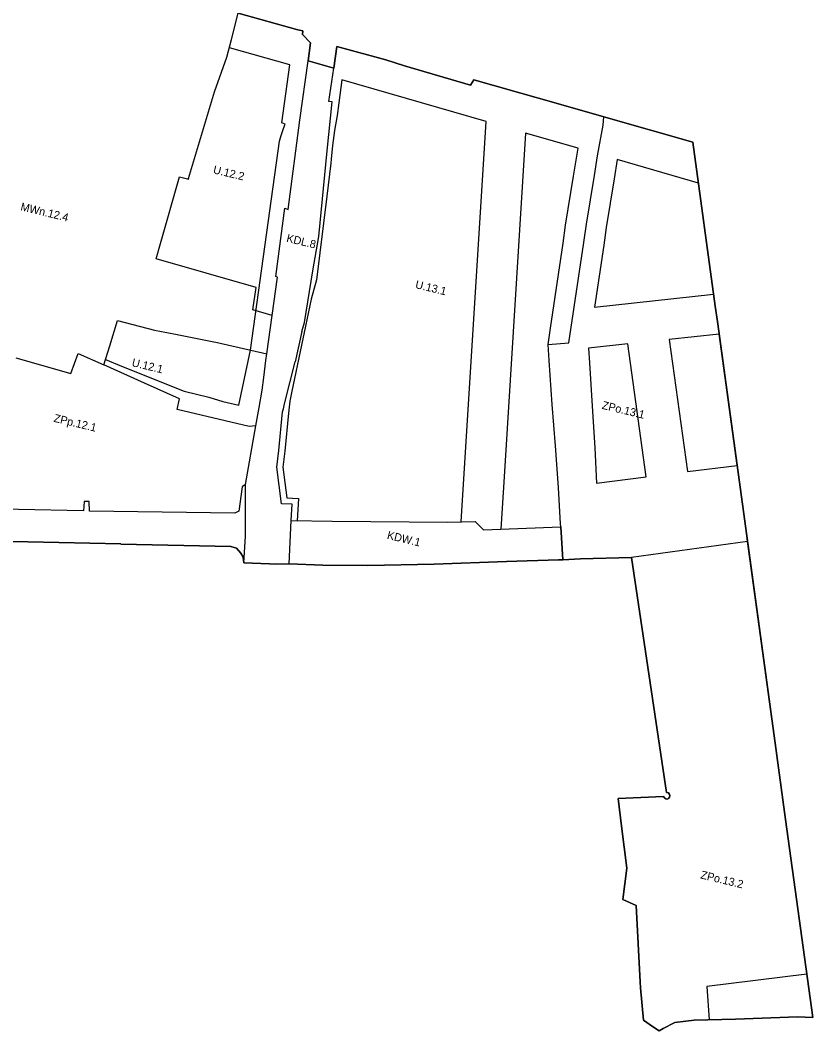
# Model space of a CAD drawing. Extents: x 7429686 to 7432896, y 5547954 to 5550600.
# Drawn here: x 7432024 to 7432420, y 5547954 to 5548459 of the extents above; entities that cross this region are included whole.
import ezdxf

# ---------------------------------------------------------------- set-up
doc = ezdxf.new("R2010")
doc.units = 0
for name, color, linetype in [('granica planu', 7, 'Continuous'), ('linie rozgraniczające', 7, 'Continuous'), ('nieprzekraczalna linia zabudowy', 7, 'Continuous'), ('obowiązująca linia zabudowy', 7, 'Continuous'), ('oznaczenia przeznaczeń', 7, 'Continuous')]:
    doc.layers.add(name, color=color, linetype=linetype)

msp = doc.modelspace()

# ---------------------------------------------------------------- linework, layer by layer
at = {"layer": 'granica planu'}
for p, q in [((7432315.39, 5548410.83), (7432359.79, 5548398.14)), ((7432359.79, 5548398.14), (7432371.02, 5548316.2)), ((7432347.59, 5548073.07), (7432346.66, 5548073.23)), ((7432346.27, 5548070.07), (7432346.93, 5548069.95)), ((7432412.06, 5547961.21), (7432381.17, 5547959.91)), ((7432419.73, 5547960.86), (7432412.06, 5547961.21))]:
    msp.add_line(p, q, dxfattribs=at)
for points in [[(7432200, 5548492.94), (7432194.33, 5548494.21), (7432194.14, 5548494.25), (7432168.86, 5548499.89), (7432167.55, 5548495.53), (7432161.04, 5548497.78), (7432158.03, 5548498.87), (7432144.51, 5548502.39), (7432143.43, 5548498.33), (7432132.81, 5548462.54), (7432162.54, 5548454.18), (7432165.08, 5548453.77), (7432164.94, 5548451.89), (7432168.88, 5548447.76), (7432167.65, 5548438.77), (7432180.47, 5548435.15), (7432182.05, 5548445.83)], [(7432182.05, 5548445.83), (7432206.42, 5548439.24), (7432215.81, 5548436.28), (7432248.72, 5548426.59), (7432250.42, 5548429.24), (7432260.46, 5548426.4), (7432273.9, 5548422.59), (7432290.34, 5548417.93), (7432315.39, 5548410.83)], [(7432371.02, 5548316.2), (7432372.06, 5548308.58), (7432386.76, 5548201.48)], [(7432303.72, 5548189.91), (7432294.92, 5548189.52), (7432292.68, 5548189.45), (7432266.77, 5548188.67), (7432230.6, 5548187.3), (7432197.45, 5548186.59), (7432175.07, 5548186.85), (7432158.14, 5548187.52), (7432151.44, 5548187.26), (7432148.44, 5548187.52), (7432135.5, 5548187.9), (7432135.19, 5548190.78), (7432134, 5548192.82), (7432131.92, 5548195.24), (7432128.99, 5548196.14), (7432074.08, 5548197.22), (7432074.05, 5548197.49), (7431996.63, 5548199.16)], [(7432386.76, 5548201.48), (7432400.46, 5548101.47), (7432406.18, 5548059.78), (7432419.73, 5547960.86)], [(7432346.66, 5548073.23), (7432329.11, 5548190.62), (7432303.72, 5548189.91)], [(7432348.09, 5548070.8), (7432348.27, 5548071.63), (7432348.19, 5548072.26), (7432347.59, 5548073.07)], [(7432326.78, 5548035.46), (7432324.19, 5548056.45), (7432322.49, 5548070.25), (7432345.23, 5548071.22)], [(7432345.23, 5548071.22), (7432345.66, 5548070.55), (7432346.27, 5548070.07)], [(7432346.93, 5548069.95), (7432347.66, 5548070.18), (7432348.09, 5548070.8)], [(7432333.76, 5547975.57), (7432333.51, 5547978.59), (7432331.44, 5548016.74), (7432324.8, 5548019.76), (7432326.78, 5548035.46)], [(7432339.64, 5547956.29), (7432335.23, 5547959.54), (7432333.76, 5547975.57)], [(7432356.29, 5547959), (7432350.86, 5547958.24), (7432344.94, 5547955.25)], [(7432381.17, 5547959.91), (7432360.54, 5547959.47), (7432356.29, 5547959)], [(7432344.94, 5547955.25), (7432342.97, 5547954.16), (7432339.64, 5547956.29)]]:
    msp.add_lwpolyline(points, dxfattribs=at)
at = {"layer": 'linie rozgraniczające'}
for p, q in [((7432164.51, 5548303.45), (7432161.17, 5548288.44)), ((7432293.81, 5548205.86), (7432294.92, 5548189.52)), ((7432294.92, 5548189.52), (7432293.81, 5548205.86)), ((7432387.16, 5548198.57), (7432329.11, 5548190.62)), ((7432303.72, 5548189.91), (7432329.11, 5548190.62)), ((7432329.11, 5548190.62), (7432329.11, 5548190.62))]:
    msp.add_line(p, q, dxfattribs=at)
for points in [[(7432129.43, 5548449.47), (7432132.81, 5548462.54)], [(7432167.65, 5548438.77), (7432168.88, 5548447.76), (7432164.94, 5548451.89), (7432165.08, 5548453.77), (7432162.54, 5548454.18), (7432132.81, 5548462.54)], [(7432127.14, 5548440.6), (7432129.43, 5548449.47)], [(7432315.39, 5548410.83), (7432290.34, 5548417.93), (7432273.9, 5548422.59), (7432260.46, 5548426.4), (7432250.42, 5548429.24), (7432248.72, 5548426.59), (7432215.81, 5548436.28), (7432206.42, 5548439.24), (7432182.05, 5548445.83), (7432180.47, 5548435.15)], [(7432120.85, 5548423.2), (7432127.14, 5548440.6)], [(7432163.59, 5548409.04), (7432167.65, 5548438.77)], [(7432180.47, 5548435.15), (7432167.65, 5548438.77)], [(7432178.01, 5548418.43), (7432180.47, 5548435.15)], [(7432107.91, 5548379.99), (7432120.85, 5548423.2)], [(7432177.2, 5548393.77), (7432179.67, 5548418.18)], [(7432179.67, 5548418.18), (7432178.01, 5548418.43)], [(7432315, 5548406.65), (7432315.39, 5548410.83)], [(7432387.16, 5548198.57), (7432386.76, 5548201.48), (7432372.06, 5548308.58), (7432371.02, 5548316.2), (7432359.79, 5548398.14), (7432315.39, 5548410.83)], [(7432157.64, 5548364.43), (7432163.59, 5548409.04)], [(7432312.25, 5548391.26), (7432315, 5548406.65)], [(7432173, 5548350.95), (7432177.2, 5548393.77)], [(7432310.65, 5548381.39), (7432312.25, 5548391.26)], [(7432093.96, 5548347.55), (7432103.51, 5548380.71)], [(7432103.51, 5548380.71), (7432108.12, 5548379.63)], [(7432306.71, 5548357.06), (7432310.65, 5548381.39)], [(7432108.12, 5548379.63), (7432107.91, 5548379.99)], [(7432151.48, 5548330.99), (7432155.98, 5548365.13)], [(7432155.98, 5548365.13), (7432157.64, 5548364.43)], [(7432305.4, 5548348.05), (7432306.71, 5548357.06)], [(7432170.04, 5548333.88), (7432173, 5548350.95)], [(7432091.75, 5548339.87), (7432093.96, 5548347.55)], [(7432297.96, 5548297.79), (7432305.4, 5548348.05)], [(7432141.7, 5548325.55), (7432091.75, 5548339.87)], [(7432149.7, 5548311.53), (7432152.44, 5548330.71)], [(7432152.44, 5548330.71), (7432151.48, 5548330.99)], [(7432165.88, 5548308.03), (7432170.04, 5548333.88)], [(7432140.08, 5548314.29), (7432141.7, 5548325.55)], [(7432149.7, 5548311.53), (7432140.08, 5548314.29)], [(7432146.97, 5548292.32), (7432149.7, 5548311.53)], [(7432068.56, 5548296.27), (7432072.44, 5548308.95)], [(7432072.44, 5548308.95), (7432090.97, 5548304.25)], [(7432164.51, 5548303.45), (7432165.88, 5548308.03)], [(7432090.97, 5548304.25), (7432101.49, 5548302.16)], [(7432101.49, 5548302.16), (7432120.55, 5548298.38)], [(7432065.69, 5548286.88), (7432068.56, 5548296.27)], [(7432120.55, 5548298.38), (7432121.55, 5548298.16)], [(7432121.55, 5548298.16), (7432146.97, 5548292.32)], [(7432287.49, 5548296.99), (7432297.96, 5548297.79)], [(7432288.13, 5548289.06), (7432287.49, 5548296.99)], [(7432021.69, 5548290.39), (7432049.22, 5548282.54)], [(7432049.22, 5548282.54), (7432052.89, 5548292.6)], [(7432052.89, 5548292.6), (7432065.69, 5548286.88)], [(7432146.53, 5548289.04), (7432146.97, 5548292.32)], [(7432086.01, 5548277.73), (7432065.69, 5548286.88)], [(7432145.5, 5548280.59), (7432146.53, 5548289.04)], [(7432155.91, 5548267.34), (7432161.17, 5548288.43)], [(7432161.17, 5548288.44), (7432161.17, 5548288.43)], [(7432289.53, 5548266.98), (7432288.13, 5548289.06)], [(7432144.64, 5548274.27), (7432145.5, 5548280.59)], [(7432103.42, 5548269.86), (7432086.01, 5548277.73)], [(7432102.32, 5548264.51), (7432103.42, 5548269.86)], [(7432143.27, 5548265.57), (7432144.64, 5548274.27)], [(7432138.31, 5548256.02), (7432102.32, 5548264.51)], [(7432141.64, 5548256.4), (7432143.27, 5548265.57)], [(7432154.89, 5548263.41), (7432155.43, 5548264.8)], [(7432155.43, 5548264.8), (7432155.91, 5548267.34)], [(7432291.15, 5548246.33), (7432289.53, 5548266.98)], [(7432153.06, 5548244.09), (7432154.89, 5548263.41)], [(7432136.42, 5548227.08), (7432141.64, 5548256.4)], [(7432141.64, 5548256.4), (7432138.31, 5548256.02)], [(7432292.74, 5548225.62), (7432291.15, 5548246.33)], [(7432152, 5548235.73), (7432153.06, 5548244.09)], [(7432154.33, 5548217.5), (7432152, 5548235.73)], [(7432134.8, 5548225.9), (7432133.1, 5548213.8)], [(7432136.42, 5548227.08), (7432134.8, 5548225.9)], [(7432136.39, 5548201.14), (7432136.42, 5548227.08)], [(7432293.7, 5548207.5), (7432292.74, 5548225.62)], [(7432055.54, 5548213.88), (7431990.34, 5548215.27)], [(7432055.87, 5548218.55), (7432055.54, 5548213.88)], [(7432058.33, 5548218.54), (7432055.87, 5548218.55)], [(7432058.47, 5548213.73), (7432058.33, 5548218.54)], [(7432159.66, 5548217.21), (7432154.33, 5548217.5)], [(7432159.25, 5548209.15), (7432159.66, 5548217.21)], [(7432131.15, 5548212.8), (7432058.47, 5548213.73)], [(7432133.1, 5548213.8), (7432131.15, 5548212.8)], [(7432158.14, 5548187.52), (7432159.25, 5548209.15)], [(7432159.25, 5548209.15), (7432179.7, 5548208.77)], [(7432179.7, 5548208.77), (7432237.44, 5548208.29)], [(7432237.44, 5548208.29), (7432251.09, 5548208.62)], [(7432251.09, 5548208.62), (7432255.28, 5548204.35)], [(7432255.28, 5548204.35), (7432293.81, 5548205.86)], [(7432293.81, 5548205.86), (7432293.7, 5548207.5)], [(7431996.63, 5548199.16), (7432074.05, 5548197.49), (7432074.08, 5548197.22), (7432128.99, 5548196.14), (7432131.92, 5548195.24), (7432134, 5548192.82), (7432135.19, 5548190.78), (7432135.5, 5548187.9)], [(7432135.5, 5548187.9), (7432136.39, 5548201.14)], [(7432329.11, 5548190.62), (7432346.66, 5548073.23), (7432347.59, 5548073.07), (7432348.19, 5548072.26), (7432348.27, 5548071.63), (7432348.09, 5548070.8), (7432347.66, 5548070.18), (7432346.93, 5548069.95), (7432346.27, 5548070.07), (7432345.66, 5548070.55), (7432345.23, 5548071.22), (7432322.49, 5548070.25), (7432324.19, 5548056.45), (7432326.78, 5548035.46), (7432324.8, 5548019.76), (7432331.44, 5548016.74), (7432333.51, 5547978.59), (7432333.76, 5547975.57), (7432335.23, 5547959.54), (7432339.64, 5547956.29), (7432342.97, 5547954.16), (7432344.94, 5547955.25), (7432350.86, 5547958.24), (7432356.29, 5547959), (7432360.54, 5547959.47), (7432381.17, 5547959.91), (7432412.06, 5547961.21), (7432419.73, 5547960.86), (7432406.18, 5548059.78), (7432400.46, 5548101.47), (7432387.16, 5548198.57)], [(7432158.14, 5548187.52), (7432175.07, 5548186.85), (7432197.45, 5548186.59), (7432230.6, 5548187.3), (7432266.77, 5548188.67), (7432292.68, 5548189.45), (7432294.92, 5548189.52)], [(7432294.92, 5548189.52), (7432303.72, 5548189.91)], [(7432303.72, 5548189.91), (7432329.11, 5548190.62)], [(7432135.5, 5548187.9), (7432148.44, 5548187.52), (7432151.44, 5548187.26), (7432158.14, 5548187.52)]]:
    msp.add_lwpolyline(points, dxfattribs=at)
at = {"layer": 'nieprzekraczalna linia zabudowy'}
for p, q in [((7432256.61, 5548408.38), (7432184.53, 5548429.32)), ((7432244.16, 5548208.45), (7432256.61, 5548408.38)), ((7432302.58, 5548395.02), (7432276.3, 5548402.66)), ((7432362.61, 5548377.58), (7432322.06, 5548389.36))]:
    msp.add_line(p, q, dxfattribs=at)
for points in [[(7432158.48, 5548436.73), (7432128.34, 5548445.25)], [(7432138.82, 5548294.19), (7432153.36, 5548398.61), (7432154.1, 5548400.85), (7432155.44, 5548404.94), (7432156.18, 5548407.17), (7432154.52, 5548407.73), (7432158.48, 5548436.73)], [(7432184.53, 5548429.32), (7432183.07, 5548417.68), (7432182.21, 5548411.46), (7432180.91, 5548403.99), (7432179.8, 5548396.48), (7432179.22, 5548389.68), (7432178.98, 5548387.6), (7432177.09, 5548371.07), (7432171.8, 5548329.29), (7432169.2, 5548319.65), (7432159.49, 5548273.67), (7432158.55, 5548268.74), (7432157.84, 5548262.72), (7432156.05, 5548243.76), (7432155.03, 5548235.74), (7432156.99, 5548220.36), (7432159.85, 5548220.2), (7432162.81, 5548220), (7432162.24, 5548208.99)], [(7432276.3, 5548402.66), (7432265.6, 5548230.97), (7432263.96, 5548204.69)], [(7432287.49, 5548296.99), (7432288.71, 5548305.2), (7432294.99, 5548347.59), (7432296.3, 5548356.67), (7432300.26, 5548381.08), (7432301.87, 5548391.04), (7432302.58, 5548395.02)], [(7432322.06, 5548389.36), (7432320.52, 5548379.79), (7432316.59, 5548355.54), (7432315.3, 5548346.6), (7432310.71, 5548315.62), (7432370.21, 5548322.08)], [(7432357.13, 5548233.51), (7432381.94, 5548236.63), (7432372.93, 5548302.26), (7432348.07, 5548299.56)], [(7432327.37, 5548297.31), (7432307.79, 5548295.18)], [(7432307.79, 5548295.18), (7432308.23, 5548287.92), (7432309.56, 5548266.21), (7432310.79, 5548245.46), (7432311.68, 5548227.78), (7432336.48, 5548230.9)], [(7432336.48, 5548230.9), (7432327.37, 5548297.31)], [(7432348.07, 5548299.56), (7432357.13, 5548233.51)], [(7432416.78, 5547982.4), (7432366.77, 5547976.35), (7432368.05, 5547959.63)]]:
    msp.add_lwpolyline(points, dxfattribs=at)
at = {"layer": 'obowiązująca linia zabudowy'}
msp.add_lwpolyline([(7432066.49, 5548289.49), (7432075.37, 5548285.91), (7432105.78, 5548273.62), (7432118.01, 5548270.68), (7432125, 5548268.46), (7432133.05, 5548266.77), (7432138.82, 5548294.19)], dxfattribs=at)

# ---------------------------------------------------------------- texts
at = {"layer": 'oznaczenia przeznaczeń'}
for s, rotation, p in [('U.12.2', 346.4891, (7432119.96, 5548382.6)), ('MWn.12.4', 346.4891, (7432023.76, 5548364.09)), ('KDL.8', 346.4891, (7432156.57, 5548348.42)), ('U.13.1', 346.4891, (7432220.92, 5548325.24)), ('U.12.1', 346.4891, (7432079.37, 5548286.25)), ('ZPo.13.1', 346.4891, (7432314.14, 5548264.95)), ('ZPp.12.1', 346.4891, (7432040.34, 5548258.48)), ('KDW.1', 346.5122, (7432206.84, 5548200.01)), ('ZPo.13.2', 346.4891, (7432363.4, 5548030.33))]:
    msp.add_text(s, height=4, rotation=rotation, dxfattribs=at).set_placement(p)

doc.saveas('drawing.dxf')
